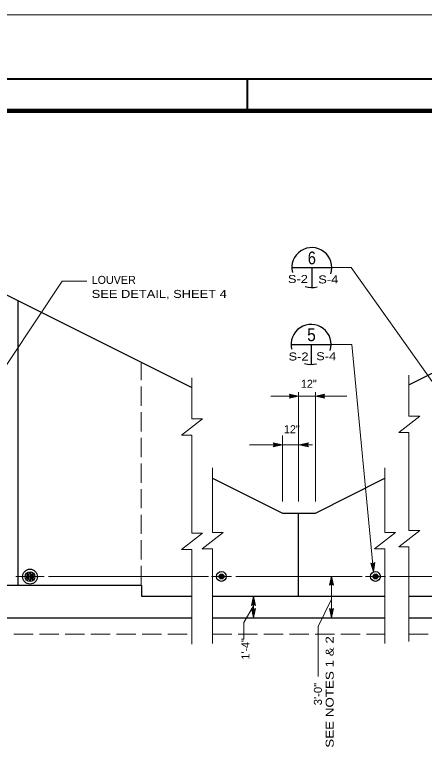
# Model space of a CAD drawing. Extents: x -22.3 to 19.7, y -11.8 to 18.2.
# Drawn here: x -0.93 to 5.45, y 6.54 to 18.16 of the extents above; entities that cross this region are included whole.
import ezdxf
from ezdxf.enums import TextEntityAlignment as Align

# ---------------------------------------------------------------- set-up
doc = ezdxf.new("R2010")
doc.units = 0
doc.header["$LTSCALE"] = 0.05
doc.linetypes.add('LONG_DASHED', pattern=[7.5, 6, -1.5])
doc.layers.add('1', color=7, linetype='Continuous', lineweight=13)
doc.layers.add('2', color=7, linetype='Continuous', lineweight=13)

msp = doc.modelspace()

# ---------------------------------------------------------------- linework, layer by layer
at = {"layer": '1', "lineweight": 40}
msp.add_line((2.69058, 17.16031), (2.69058, 16.66031), dxfattribs=at)
at = {"layer": '1'}
for p, q in [((4.31458, 14.21531), (4.01258, 14.21531)), ((7.64658, 9.51631), (4.31458, 14.21531)), ((4.32458, 13.01631), (4.00158, 13.01631)), ((4.66358, 9.46431), (4.32458, 13.01631)), ((1.83058, 12.49231), (1.83058, 11.85431)), ((5.21558, 12.53431), (5.21558, 11.89631)), ((3.49458, 12.20931), (3.35058, 12.24031)), ((3.49458, 12.20931), (3.35058, 12.17831)), ((3.45758, 12.20931), (3.36358, 12.22931)), ((3.37258, 12.20931), (3.36358, 12.22931)), ((3.45758, 12.20931), (3.36358, 12.18931)), ((3.36358, 12.18931), (3.37258, 12.20931)), ((3.42158, 12.20931), (3.37658, 12.21831)), ((3.38058, 12.20931), (3.37658, 12.21831)), ((3.42158, 12.20931), (3.37658, 12.19931)), ((3.37658, 12.19931), (3.38058, 12.20931)), ((3.49458, 10.56331), (3.49458, 12.27331)), ((3.75558, 10.56331), (3.75558, 12.27331)), ((3.75558, 12.20931), (3.89958, 12.24031)), ((3.75558, 12.20931), (3.89958, 12.17831)), ((3.79258, 12.20931), (3.88658, 12.22931)), ((3.79258, 12.20931), (3.88658, 12.18931)), ((3.82858, 12.20931), (3.87358, 12.21931)), ((3.82858, 12.20931), (3.87358, 12.20031)), ((3.87358, 12.21931), (3.86958, 12.20931)), ((3.86958, 12.20931), (3.87358, 12.20031)), ((3.88658, 12.22931), (3.87758, 12.20931)), ((3.87758, 12.20931), (3.88658, 12.18931)), ((1.67058, 11.59831), (1.99858, 11.85431)), ((1.83058, 11.85431), (1.99858, 11.85431)), ((5.05558, 11.64031), (5.38358, 11.89631)), ((5.21558, 11.89631), (5.38358, 11.89631)), ((5.05558, 11.64031), (5.21558, 11.64031)), ((5.21558, 11.64031), (5.21558, 10.11331)), ((1.67058, 11.59831), (1.83058, 11.59831)), ((1.83058, 11.59831), (1.83058, 10.07131)), ((3.24258, 10.56331), (3.24258, 11.59331)), ((3.24458, 11.45031), (3.10058, 11.48131)), ((3.24458, 11.45031), (3.10058, 11.41931)), ((3.20758, 11.45031), (3.11358, 11.47031)), ((3.12258, 11.45031), (3.11358, 11.47031)), ((3.20758, 11.45031), (3.11358, 11.43031)), ((3.11358, 11.43031), (3.12258, 11.45031)), ((3.17158, 11.45031), (3.12658, 11.45931)), ((3.13058, 11.45031), (3.12658, 11.45931)), ((3.17158, 11.45031), (3.12658, 11.44031)), ((3.12658, 11.44031), (3.13058, 11.45031)), ((3.50258, 11.45031), (3.64658, 11.48131)), ((3.50258, 11.45031), (3.64658, 11.41931)), ((3.50258, 11.45031), (3.71258, 11.45031)), ((3.53958, 11.45031), (3.63358, 11.47031)), ((3.53958, 11.45031), (3.63358, 11.43031)), ((3.57558, 11.45031), (3.62058, 11.46031)), ((3.57558, 11.45031), (3.62058, 11.44131)), ((3.62058, 11.46031), (3.61658, 11.45031)), ((3.61658, 11.45031), (3.62058, 11.44131)), ((3.63358, 11.47031), (3.62458, 11.45031)), ((3.62458, 11.45031), (3.63358, 11.43031)), ((2.15258, 11.09131), (2.15258, 10.07931)), ((4.83958, 11.09131), (4.83958, 10.07931)), ((5.05558, 9.85731), (5.38358, 10.11331)), ((5.21558, 10.11331), (5.38358, 10.11331)), ((1.67058, 9.81531), (1.99858, 10.07131)), ((1.83058, 10.07131), (1.99858, 10.07131)), ((1.99258, 9.82331), (2.32058, 10.07931)), ((2.15258, 10.07931), (2.32058, 10.07931)), ((4.67958, 9.82331), (5.00758, 10.07931)), ((4.83958, 10.07931), (5.00758, 10.07931)), ((1.67058, 9.81531), (1.83058, 9.81531)), ((1.83058, 9.81531), (1.83058, 8.33731)), ((1.99258, 9.82331), (2.15258, 9.82331)), ((2.15258, 9.82331), (2.15258, 8.34531)), ((4.67958, 9.82331), (4.83958, 9.82331)), ((4.83958, 9.82331), (4.83958, 8.34531)), ((5.05558, 9.85731), (5.21558, 9.85731)), ((5.21558, 9.85731), (5.21558, 8.37931)), ((4.66358, 9.46431), (4.61858, 9.60431)), ((4.65958, 9.50131), (4.63158, 9.59331)), ((4.63158, 9.59331), (4.65158, 9.58531)), ((4.65658, 9.53731), (4.64258, 9.58131)), ((4.64258, 9.58131), (4.65258, 9.57731)), ((4.65158, 9.58531), (4.67058, 9.59631)), ((4.65258, 9.57731), (4.66158, 9.58231)), ((4.65658, 9.53731), (4.66158, 9.58231)), ((4.65958, 9.50131), (4.67058, 9.59631)), ((4.66358, 9.46431), (4.68058, 9.61031)), ((-0.91242, 9.39231), (-0.47342, 9.39231)), ((-0.40642, 9.39231), (2.09058, 9.39231)), ((2.13658, 9.39231), (2.44658, 9.39231)), ((2.51358, 9.39231), (4.48558, 9.39231)), ((4.00958, 9.40131), (3.97858, 9.25731)), ((4.00958, 9.36431), (3.98958, 9.27031)), ((4.00958, 9.32831), (4.00058, 9.28331)), ((4.00958, 8.74831), (4.00958, 9.40131)), ((4.00958, 9.40131), (4.04058, 9.25731)), ((4.00958, 9.36431), (4.02958, 9.27031)), ((4.00958, 9.32831), (4.01958, 9.28331)), ((4.53758, 9.39231), (4.84758, 9.39231)), ((4.91658, 9.39231), (7.43958, 9.39231)), ((4.00958, 9.27931), (3.98958, 9.27031)), ((4.00958, 9.28731), (4.00058, 9.28331)), ((4.01958, 9.28331), (4.00958, 9.28731)), ((4.02958, 9.27031), (4.00958, 9.27931)), ((2.79058, 9.08631), (2.75958, 8.94231)), ((2.79058, 8.74831), (2.79058, 9.08631)), ((2.79058, 9.08631), (2.82158, 8.94231)), ((2.79058, 9.04931), (2.77058, 8.95531)), ((2.79058, 8.96431), (2.77058, 8.95531)), ((2.79058, 9.01331), (2.78158, 8.96831)), ((2.79058, 8.97231), (2.78158, 8.96831)), ((2.79058, 9.04931), (2.81058, 8.95531)), ((2.79058, 9.01331), (2.80058, 8.96831)), ((2.80058, 8.96831), (2.79058, 8.97231)), ((2.81058, 8.95531), (2.79058, 8.96431)), ((4.00958, 9.03931), (3.79958, 8.61331)), ((2.79058, 8.93331), (2.64158, 8.67431)), ((2.79058, 8.74831), (2.75958, 8.89231)), ((2.79058, 8.78531), (2.77058, 8.87931)), ((2.77058, 8.87931), (2.79058, 8.87031)), ((2.79058, 8.82131), (2.78058, 8.86631)), ((2.78058, 8.86631), (2.79058, 8.86231)), ((2.79058, 8.74831), (2.82158, 8.89231)), ((2.79058, 8.78531), (2.81058, 8.87931)), ((2.79058, 8.87031), (2.81058, 8.87931)), ((2.79058, 8.82131), (2.79958, 8.86631)), ((2.79058, 8.86231), (2.79958, 8.86631)), ((4.00958, 8.74831), (3.97858, 8.89231)), ((4.00958, 8.78531), (3.98958, 8.87931)), ((3.98958, 8.87931), (4.00958, 8.87031)), ((4.00958, 8.82131), (3.99958, 8.86631)), ((3.99958, 8.86631), (4.00958, 8.86231)), ((4.00958, 8.74831), (4.04058, 8.89231)), ((4.00958, 8.78531), (4.02958, 8.87931)), ((4.00958, 8.87031), (4.02958, 8.87931)), ((4.00958, 8.82131), (4.01858, 8.86631)), ((4.00958, 8.86231), (4.01858, 8.86631)), ((2.64158, 8.67431), (2.64158, 8.41731)), ((3.79958, 8.61331), (3.79958, 7.83231))]:
    msp.add_line(p, q, dxfattribs=at)
at = {"layer": '1', "lineweight": 25}
for p, q in [((-0.87842, 9.25831), (-0.87842, 13.69831)), ((2.15258, 10.92931), (3.24258, 10.38231)), ((3.49458, 9.08631), (3.49458, 10.38231)), ((-0.72442, 9.34931), (-0.72442, 9.43431)), ((-0.70642, 9.34031), (-0.70642, 9.44431)), ((-0.67942, 9.33931), (-0.67942, 9.44431)), ((-0.65742, 9.34931), (-0.65742, 9.43431)), ((2.27258, 9.37431), (2.27258, 9.41631)), ((2.28358, 9.36731), (2.28358, 9.42131)), ((2.29758, 9.36731), (2.29758, 9.42131)), ((2.30958, 9.37431), (2.30958, 9.41631)), ((4.67358, 9.37431), (4.67358, 9.41631)), ((4.68458, 9.36731), (4.68458, 9.42131)), ((4.69858, 9.36731), (4.69858, 9.42131)), ((4.71058, 9.37431), (4.71058, 9.41631)), ((1.04358, 9.08631), (1.83058, 9.08631)), ((2.15258, 9.08631), (4.83958, 9.08631)), ((5.21558, 9.08631), (5.96158, 9.08631)), ((-17.03142, 8.74831), (1.83058, 8.74831)), ((2.15258, 8.74831), (4.83958, 8.74831)), ((5.21558, 8.74831), (9.38858, 8.74831))]:
    msp.add_line(p, q, dxfattribs=at)
at = {"layer": '1', "linetype": 'LONG_DASHED'}
for p, q in [((1.03958, 9.25831), (1.03958, 12.72631)), ((-0.94442, 8.49131), (1.83058, 8.49131)), ((2.15258, 8.49131), (4.83958, 8.49131)), ((5.21558, 8.49131), (7.98458, 8.49131))]:
    msp.add_line(p, q, dxfattribs=at)
at = {"layer": '1'}
for points in [[(-22.30942, 18.16031), (19.69058, 18.16031), (19.69058, -11.83969)], [(-2.64042, 10.32031), (-0.19342, 14.00631), (0.19158, 14.00631)], [(3.05958, 12.20931), (3.49458, 12.20931), (3.75558, 12.20931), (4.24658, 12.20931)], [(3.35058, 12.17831), (3.36458, 12.20931), (3.35058, 12.24031)], [(3.89958, 12.24031), (3.88558, 12.20931), (3.89958, 12.17831)], [(2.72658, 11.45031), (3.24458, 11.45031), (3.50258, 11.45031)], [(3.10058, 11.41931), (3.11458, 11.45031), (3.10058, 11.48131)], [(3.64658, 11.48131), (3.63258, 11.45031), (3.64658, 11.41931)], [(4.61858, 9.60431), (4.65158, 9.59331), (4.68058, 9.61031)], [(4.04058, 9.25731), (4.00958, 9.27131), (3.97858, 9.25731)], [(2.82158, 8.94231), (2.79058, 8.95631), (2.75958, 8.94231)], [(2.75958, 8.89231), (2.79058, 8.87831), (2.82158, 8.89231)], [(3.97858, 8.89231), (4.00958, 8.87831), (4.04058, 8.89231)]]:
    msp.add_lwpolyline(points, dxfattribs=at)
at = {"layer": '1', "lineweight": 40}
msp.add_lwpolyline([(-21.30942, -10.83969), (-21.30942, 17.16031), (18.69058, 17.16031), (18.69058, -10.83969)], close=True, dxfattribs=at)
at = {"layer": '1', "lineweight": 90}
msp.add_lwpolyline([(-19.80942, 16.66031), (18.19058, 16.66031), (18.19058, -10.33969), (-19.80942, -10.33969)], close=True, dxfattribs=at)
at = {"layer": '1', "lineweight": 25}
for points in [[(5.21558, 12.38531), (8.11158, 13.82531), (9.37358, 13.82531)], [(-17.03142, 8.74831), (-17.03142, 9.37931), (-8.17942, 13.81631), (-1.11242, 13.81631), (1.83058, 12.34331)], [(3.24258, 10.38231), (3.75558, 10.38231), (4.83958, 10.92931)], [(-17.03142, 9.07131), (-10.35942, 9.07131), (-10.35942, 9.25831), (1.04358, 9.25831), (1.04358, 9.08631)]]:
    msp.add_lwpolyline(points, dxfattribs=at)
for centre, radius in [((-0.69242, 9.39231), 0.11574), ((-0.69242, 9.39231), 0.07571), ((2.29158, 9.39431), 0.07624), ((2.29158, 9.39431), 0.03821), ((4.69258, 9.39431), 0.07624), ((4.69258, 9.39431), 0.03821)]:
    msp.add_circle(centre, radius, dxfattribs=at)
for centre, radius, start, end in [((-0.69242, 9.39231), 0.05401, 126.02737, 233.1301), ((-0.69242, 9.39231), 0.05401, 75.96376, 104.03624), ((-0.69242, 9.39231), 0.05401, 309.80557, 48.81408), ((2.29158, 9.39431), 0.02802, 130.60129, 226.4688), ((2.29158, 9.39431), 0.02802, 77.47119, 106.50436), ((2.29158, 9.39431), 0.02802, 310.60129, 50.71059), ((4.69258, 9.39431), 0.02802, 130.60129, 226.4688), ((4.69258, 9.39431), 0.02802, 77.47119, 106.50436), ((4.69258, 9.39431), 0.02802, 310.60129, 50.71059), ((-0.69242, 9.39231), 0.05401, 254.93151, 282.75753), ((2.29158, 9.39431), 0.02802, 251.56505, 282.09476), ((4.69258, 9.39431), 0.02802, 251.56505, 282.09476)]:
    msp.add_arc(centre, radius, start, end, dxfattribs=at)
at = {"layer": '2', "lineweight": 25}
for p, q in [((3.38858, 14.21531), (4.01258, 14.21531)), ((3.70058, 14.21531), (3.70058, 13.90331)), ((3.37758, 13.01631), (4.00158, 13.01631)), ((3.68958, 13.01631), (3.68958, 12.70431))]:
    msp.add_line(p, q, dxfattribs=at)
for centre, start, end in [((3.70058, 14.21531), 341.96976, 193.81208), ((3.70058, 14.21531), 251.04049, 285.74671), ((3.68958, 13.01631), 341.96976, 193.81208), ((3.68958, 13.01631), 251.04049, 285.74671)]:
    msp.add_arc(centre, 0.3125, start, end, dxfattribs=at)

# ---------------------------------------------------------------- texts
at = {"layer": '1'}
msp.add_text('LOUVER', height=0.125, dxfattribs=at).set_placement((0.26858, 13.96131))
at = {"layer": '1', "width": 1.2}
msp.add_text('SEE DETAIL, SHEET 4', height=0.125, dxfattribs=at).set_placement((0.26858, 13.74231))
at = {"layer": '1'}
for p in [(3.65408, 12.33931), (3.38908, 11.63031)]:
    msp.add_text('12"', height=0.125, dxfattribs=at).set_placement(p, align=Align.CENTER)
msp.add_text('1\'-4"', height=0.125, rotation=90, dxfattribs=at).set_placement((2.72858, 8.43031), align=Align.RIGHT)
for s, width, p in [('SEE NOTES 1 & 2', 1.25, (4.04158, 8.46231)), ('3\'-0"', 1.05, (3.85758, 7.73331))]:
    msp.add_text(s, height=0.125, rotation=90, dxfattribs=dict(at, width=width)).set_placement(p, align=Align.RIGHT)
at = {"layer": '2'}
for s, height, width, p in [('6', 0.2, 0.85, (3.70058, 14.26631)), ('S-2', 0.125, 1.2, (3.48358, 13.97531)), ('S-4', 0.125, 1.2, (3.95658, 13.96831)), ('5', 0.2, 0.9, (3.69508, 13.06731)), ('S-4', 0.125, 1.2, (3.92458, 12.76931)), ('S-2', 0.125, 1.2, (3.49358, 12.76531))]:
    msp.add_text(s, height=height, dxfattribs=dict(at, width=width)).set_placement(p, align=Align.CENTER)

doc.saveas('drawing.dxf')
